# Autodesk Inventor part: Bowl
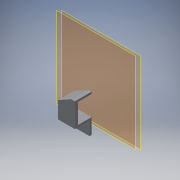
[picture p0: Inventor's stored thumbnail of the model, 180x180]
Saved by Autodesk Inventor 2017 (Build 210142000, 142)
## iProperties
Created: 2017-05
Part Number: Bowl
Material: Generic
Document SubType Name: Modeling
Designer: 1460374
Density: 1 g/cm^3
Appearance: Default
Author: 1460374
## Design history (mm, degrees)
workplane "Work Plane1"
sketch "Sketch1"
  geometry: L1 (6.014, 0)-(6.014, 25.4); L2 (6.014, 25.4)-(28.554, 37.872); L3 (28.554, 37.872)-(34.273, 37.872); L4 (6.014, 0)-(34.273, 0); L5 (34.273, 41.769)-(27.547, 41.769); L6 (27.547, 41.769)-(2.117, 27.698); L7 (2.117, 27.698)-(2.117, -3.897); L8 (2.117, -3.897)-(34.273, -3.897); L9 (34.273, 41.769)-(34.273, 37.872); L10 (34.273, 0)-(34.273, -3.897); 1 further point
  constraints: 20 end point, 2 perpendicular, 2 vertical, 1 collinear, 1 horizontal, 3 other
  dimensions: "d0" = 25.4 distance of L1.start L1.end
extrude "Extrusion1" new body sketch "Sketch1" distance "d1" = 31.75; taper "d2" = 0 deg
workplane "Work Plane2"
sketch "Sketch3"
  geometry: L1 (0, 25.4)-(-31.75, 25.4) reference; L2 (-31.75, 0)-(-26.025, 0); L3 (-26.025, 0)-(-26.025, 25.4); L4 (-26.025, 25.4)-(-31.75, 25.4); L5 (-31.75, 25.4)-(-31.75, 0); 1 further point
  constraints: 8 end point, 2 parallel, 1 horizontal, 1 perpendicular, 1 point on line
extrude "Extrusion3" join sketch "Sketch3" stored distance "d8" = 28.575; taper "d9" = 0 deg
sketch "Sketch4"
  geometry: L1 (0, 0)-(0, -5.725) reference; L2 (0, -5.725)-(0, 0); L3 (0, 0)-(28.259, 0); L4 (28.259, -5.725)-(28.259, 0) reference; L5 (28.259, 0)-(28.259, -5.725); L6 (28.259, -5.725)-(0, -5.725); 1 further point
  constraints: 8 end point, 2 point on line, 1 collinear, 1 perpendicular
extrude "Extrusion4" join sketch "Sketch4" distance "d10" = 14.2875; taper "d11" = 0 deg
sketch "Sketch5"
  geometry: L1 (6.014, 29.854)-(23.786, 39.688) reference; L2 (6.014, 39.688)-(23.786, 39.688) reference; L3 (23.786, 39.688)-(6.014, 39.688); L4 (6.014, 29.854)-(6.014, 39.688) reference; L5 (6.014, 39.688)-(6.014, 29.854); 1 further point
  constraints: 4 end point, 2 collinear
extrude "Extrusion5" cut sketch "Sketch5" distance "d12" = 9.525; taper "d13" = 0 deg
sketch "Sketch6"
  geometry: L1 (0, 3.897)-(-26.025, 3.897) reference; L2 (-26.025, 3.897)-(-26.025, 0); L3 (0, 0)-(-31.75, 0) reference; L4 (0, 0)-(0, 3.897) reference; L5 (0, 3.897)-(0, 0); L6 (0, 0)-(-26.025, 0)
  constraints: 6 end point, 1 collinear, 1 perpendicular, 1 point on line, 1 vertical
extrude "Extrusion6" cut sketch "Sketch6" distance "d14" = 20.6375; taper "d15" = 0 deg
sketch "Sketch7"
  geometry: L1 (0, 3.897)-(0, 0) reference; L2 (-26.025, 3.897)-(0, 3.897) reference; L3 (0, 0)-(-26.025, 0); L4 (-26.025, 0)-(-26.025, 3.897); L5 (-26.025, 3.897)-(0, 3.897); L6 (0, 3.897)-(0, 0)
  constraints: 8 end point, 2 parallel, 1 horizontal, 1 perpendicular
extrude "Extrusion7" join sketch "Sketch7" stored distance "d16" = 25.4; taper "d17" = 0 deg
sketch "Sketch8"
  geometry: L1 (32.156, -31.75)-(32.156, 0) reference; L2 (0, -31.75)-(32.156, -31.75); L3 (32.156, -31.75)-(32.156, -27.771); L4 (32.156, -27.771)-(0, -27.771); L5 (0, -27.771)-(0, -31.75); 1 further point
  constraints: 8 end point, 2 parallel, 1 horizontal, 1 perpendicular, 1 point on line
extrude "Extrusion8" join sketch "Sketch8" distance "d18" = 25.4; taper "d19" = 0 deg
body "Solid1"
